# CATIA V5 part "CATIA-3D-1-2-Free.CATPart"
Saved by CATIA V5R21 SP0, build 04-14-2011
Part number: CATIA-3D-1-2-Free
Bounding box of the stored display mesh (mm): x -56 to 64, y -37.5 to 37.5, z -25 to 50
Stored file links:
  C:\Users\Rasoul Mohammadi\Desktop\CATIA-Free\3D\CATIA-3D-1-2-Free.CATPart
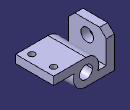
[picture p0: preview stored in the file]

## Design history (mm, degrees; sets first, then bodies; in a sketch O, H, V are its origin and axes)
Body1 (main body)
  Sketch1 on zx-plane, origin (0, 0, 0), H (-1, 0, 0), V (0, 0, 1)
    arc A1 centre (0, 0) radius 25 from (23.3238, -9) to (0, 25) ccw
    point P1 (0, 25)
    line L1 (0, 25) -> (-64, 25)
    line L2 (-64, 25) -> (-64, 9)
    line L3 (-64, 9) -> (-23.3238, 9)
    point P4 (-23.3238, 9)
    point P5 (0, -25)
    line L4 (0, -25) -> (56, -25)
    line L5 (56, -25) -> (56, 50)
    line L6 (56, 50) -> (40, 50)
    line L7 (40, 50) -> (40, -9)
    line L8 (40, -9) -> (23.3238, -9)
    arc A2 centre (0, 0) radius 25 from (-23.3238, 9) to (0, -25) ccw
    circle A3 centre (0, 0) radius 12.5
    radius A1 = 25
    length L2 = 16
    distance V L2 = 64
    distance V L5 = 56
    length L6 = 16
    length L7 = 59
    length L5 = 75
    radius A3 = 12.5
    coincidence: P1 V, P4 A1, P5 V, A1 A2
    tangency: L1 A1, L4 A1
    vertical: L2 V, L5 V, L7 V
    horizontal: L3 H, L6 H, L8 H
  Pad1: profile Sketch1, direction (0, 1, 0), length 37.5, mirrored extent
  Sketch2 on face of Pad1 from Sketch1.L1, origin (51.0094, -22.2767, 25), H (1, 0, 0), V (0, 1, 0)
    point P1 (-3.0094, 0.7767)
    reference projected line E1 (-51.0094, -15.2233) -> (12.9906, -15.2233) from edge [start face of Pad1 | face of Pad1 from Sketch1.L1]
    reference projected line E2 (12.9906, -15.2233) -> (12.9906, 59.7767) from edge [face of Pad1 from Sketch1.L2 | face of Pad1 from Sketch1.L1]
    distance E1 P1 = 16
    distance P1 E2 = 16
  Hole1: placed by Sketch2, at (48, -21.5, 25) direction (0, 0, -1), diameter 12, through (limit type 6)
  Mirror1: of Hole1, about zx-plane
  Sketch3 on face of Pad1 from Sketch1.L7, origin (-40, 5.5493, 24.8654), H (0, 1, 0), V (0, 0, 1)
    point P1 (-5.5493, 0.1346)
    reference projected line E1 (-43.0493, 25.1346) -> (-43.0493, -33.8654) from edge [start face of Pad1 | face of Pad1 from Sketch1.L7]
    reference projected line E2 (-43.0493, 25.1346) -> (31.9507, 25.1346) from edge [face of Pad1 from Sketch1.L7 | face of Pad1 from Sketch1.L6]
    distance P1 E1 = 37.5
    distance E2 P1 = 25
  Hole2: placed by Sketch3, at (-40, 0, 25) direction (-1, 0, 0), diameter 25, through (limit type 6)
  Chamfer1: length 13, angle 45, on edge [face of Pad1 from Sketch1.L6 | end face of Pad1]; edge [start face of Pad1 | face of Pad1 from Sketch1.L6]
